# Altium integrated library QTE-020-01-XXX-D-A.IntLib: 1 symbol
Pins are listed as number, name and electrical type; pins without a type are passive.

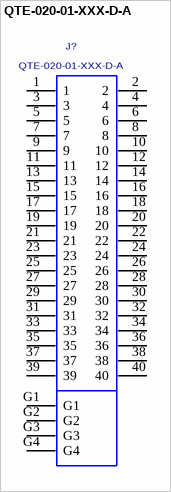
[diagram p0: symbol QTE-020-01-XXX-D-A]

## QTE-020-01-XXX-D-A
designator J?
HIGH SPEED TERMINAL STRIP, .8mm PITCH, 40 PINS.; MANUFACTURER: SAMTEC, INC.
footprint QTE-020-01-XXX-D-A
pins: 1, 2, 3, 4, 5, 6, 7, 8, 9, 10, 11, 12, 13, 14, 15, 16, 17, 18, 19, 20, 21, 22, 23, 24, 25, 26, 27, 28, 29, 30, 31, 32, 33, 34, 35, 36, 37, 38, 39, 40, G1, G2, G3, G4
